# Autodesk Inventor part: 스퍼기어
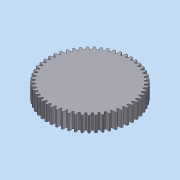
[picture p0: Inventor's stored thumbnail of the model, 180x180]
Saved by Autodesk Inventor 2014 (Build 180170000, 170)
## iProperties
Created: 2011-04
Part Number: 스퍼기어
Material: 강
Document SubType Name: Modeling
Designer: pww
Categories: <?xml version="1.0" encoding="UTF-16"?> <MemberInstance><Categories><FamilyTemplate><FamilyTemplateParameter ValueType="xs:double" Id="1" ObjectReferenceKey="da
Density: 1 g/cm^3
Appearance: 강철
CustomPartVersion: 1
Author: pww
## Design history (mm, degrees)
sketch "Sketch1"
  geometry: C1 r 55 at (0, 0)
  constraints: 1 centre point
  dimensions: "d0" = 110 diameter of C1 (= da_da)
extrude "Extrusion1" new body sketch "Sketch1" distance "d1" = 20 (= da_b); taper "d2" = 0 deg
workplane "Work Plane2"
feature "피치 지름" dims "d4" = 10, "d5" = 0
workplane "Work Plane8"
workplane "Work Plane9"
feature "스퍼 기어" dims "da_b" = 20, "da_d" = 106, "da_aw" = 80, "da_da" = 110, "da_df" = 101, "da_dw" = 106, angle "da_beta" = 0 deg, "da_lefttooth" = 0, "da_righttooth" = 0
body "Solid1"
sketch "Sketch2"
  geometry: C1 r 55 at (0, 0) reference; C2 r 53 at (0, 0)
  constraints: 1 centre point, 1 coincident
  dimensions: "d3" = 106 diameter of C2 (= da_dw)
body "Srf1"
other parameters: "d17" = 0, "d34" = 0.59275 (computed from da_z), "d39" = 0, "d41" = 0, "d47" = 0, "d48" = 0
